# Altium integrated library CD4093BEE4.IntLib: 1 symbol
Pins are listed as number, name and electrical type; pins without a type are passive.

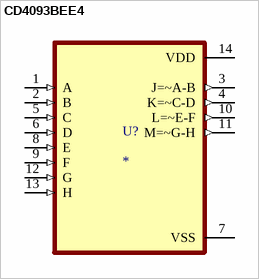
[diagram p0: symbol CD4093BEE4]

## CD4093BEE4
designator U?
CMOS Quad 2-Input NAND Schmitt Triggers 14-PDIP -55 to 125; MF: Texas Instruments; MP: CD4093BEE4
footprint DIP794W45P254L1969H508Q14
pins: 1 A (in), 2 B (in), 3 J=~A-B (out), 4 K=~C-D (out), 5 C (in), 6 D (in), 7 VSS (power), 8 E (in), 9 F (in), 10 L=~E-F (out), 11 M=~G-H (out), 12 G (in), 13 H (in), 14 VDD (power)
